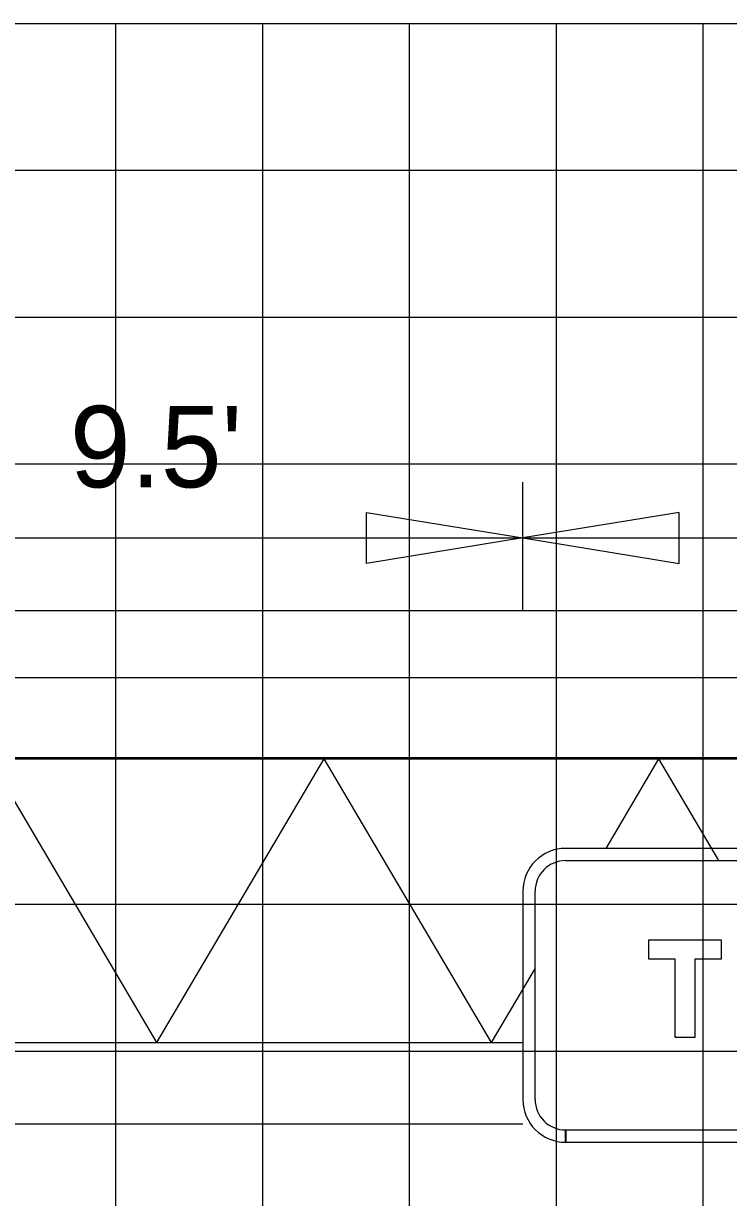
# Model space of a CAD drawing. Extents: x 2193008 to 2198143, y 1236112 to 1237864.
# Drawn here: x 2195635.45 to 2195645.05, y 1237302.11 to 1237318.11 of the extents above; entities that cross this region are included whole.
import ezdxf

# ---------------------------------------------------------------- set-up
doc = ezdxf.new("R2010")
doc.units = 0
for name, color, linetype in [('GSBWFILL', 7, 'Continuous'), ('GSCOLORFILL', 7, 'Continuous'), ('GSDIMS', 7, 'Continuous'), ('GSOUTLINE', 7, 'Continuous'), ('Level 55', 7, 'Continuous'), ('M-ROADS', 7, 'Continuous')]:
    doc.layers.add(name, color=color, linetype=linetype)

msp = doc.modelspace()

# ---------------------------------------------------------------- linework, layer by layer
at = {"layer": 'GSBWFILL'}
msp.add_lwpolyline([(2195644.59, 1237304.291), (2195644.324, 1237304.291), (2195644.324, 1237305.356), (2195643.964, 1237305.356), (2195643.964, 1237305.623), (2195644.95, 1237305.623), (2195644.95, 1237305.356), (2195644.59, 1237305.356)], close=True, dxfattribs=at)
at = {"layer": 'GSCOLORFILL'}
for p, q in [((2195658.15, 1237306.867), (2195642.832, 1237306.867)), ((2195642.832, 1237306.701), (2195658.15, 1237306.701)), ((2195642.249, 1237306.284), (2195642.249, 1237303.446)), ((2195642.416, 1237303.446), (2195642.416, 1237306.284)), ((2195642.832, 1237302.863), (2195642.832, 1237303.029)), ((2195658.15, 1237303.029), (2195642.834, 1237303.029)), ((2195642.834, 1237303.029), (2195642.834, 1237302.863)), ((2195642.834, 1237302.863), (2195658.15, 1237302.863))]:
    msp.add_line(p, q, dxfattribs=at)
msp.add_lwpolyline([(2195644.59, 1237304.291), (2195644.324, 1237304.291), (2195644.324, 1237305.356), (2195643.964, 1237305.356), (2195643.964, 1237305.623), (2195644.95, 1237305.623), (2195644.95, 1237305.356), (2195644.59, 1237305.356)], close=True, dxfattribs=at)
for centre, radius, start, end in [((2195642.832, 1237306.284), 0.583, 90, 180), ((2195642.832, 1237306.284), 0.416, 90, 180), ((2195642.832, 1237303.446), 0.583, 180, 270), ((2195642.832, 1237303.446), 0.416, 180, 270)]:
    msp.add_arc(centre, radius, start, end, dxfattribs=at)
at = {"layer": 'GSDIMS'}
for p, q in [((2195642.249, 1237310.114), (2195642.249, 1237311.855)), ((2195632.704, 1237311.097), (2195642.249, 1237311.097)), ((2195642.249, 1237311.097), (2195658.737, 1237311.097)), ((2195632.704, 1237309.196), (2195647.249, 1237309.196)), ((2195632.704, 1237308.086), (2195647.249, 1237308.086)), ((2195634.982, 1237308.086), (2195637.261, 1237304.223)), ((2195639.54, 1237308.086), (2195637.261, 1237304.223)), ((2195639.54, 1237308.086), (2195641.818, 1237304.223)), ((2195644.097, 1237308.086), (2195643.378, 1237306.867)), ((2195644.097, 1237308.086), (2195644.914, 1237306.701)), ((2195642.416, 1237305.236), (2195641.818, 1237304.223)), ((2195632.704, 1237304.223), (2195642.249, 1237304.223)), ((2195632.704, 1237303.113), (2195642.249, 1237303.113))]:
    msp.add_line(p, q, dxfattribs=at)
for points in [[(2195642.249, 1237311.097), (2195640.121, 1237310.75), (2195640.121, 1237311.445)], [(2195642.249, 1237311.097), (2195644.378, 1237310.75), (2195644.378, 1237311.445)]]:
    msp.add_lwpolyline(points, close=True, dxfattribs=at)
at = {"layer": 'GSOUTLINE'}
msp.add_lwpolyline([(2195644.59, 1237304.291), (2195644.324, 1237304.291), (2195644.324, 1237305.356), (2195643.964, 1237305.356), (2195643.964, 1237305.623), (2195644.95, 1237305.623), (2195644.95, 1237305.356), (2195644.59, 1237305.356)], close=True, dxfattribs=at)
at = {"layer": 'M-ROADS'}
for p, q in [((2195584.707, 1237318.106), (2195714.707, 1237318.106)), ((2195636.707, 1237258.106), (2195636.707, 1237318.106)), ((2195638.707, 1237258.106), (2195638.707, 1237318.106)), ((2195640.707, 1237258.106), (2195640.707, 1237318.106)), ((2195642.707, 1237258.106), (2195642.707, 1237318.106)), ((2195644.707, 1237258.106), (2195644.707, 1237318.106)), ((2195584.707, 1237316.106), (2195714.707, 1237316.106)), ((2195584.707, 1237314.106), (2195714.707, 1237314.106)), ((2195584.707, 1237312.106), (2195714.707, 1237312.106)), ((2195584.707, 1237310.106), (2195714.707, 1237310.106)), ((2195584.707, 1237308.106), (2195714.707, 1237308.106)), ((2195584.707, 1237306.106), (2195714.707, 1237306.106)), ((2195584.707, 1237304.106), (2195714.707, 1237304.106))]:
    msp.add_line(p, q, dxfattribs=at)

# ---------------------------------------------------------------- texts
at = {"layer": 'Level 55'}
msp.add_text("9.5'", height=1.1105, dxfattribs=at).set_placement((2195636.081, 1237311.786))

doc.saveas('drawing.dxf')
